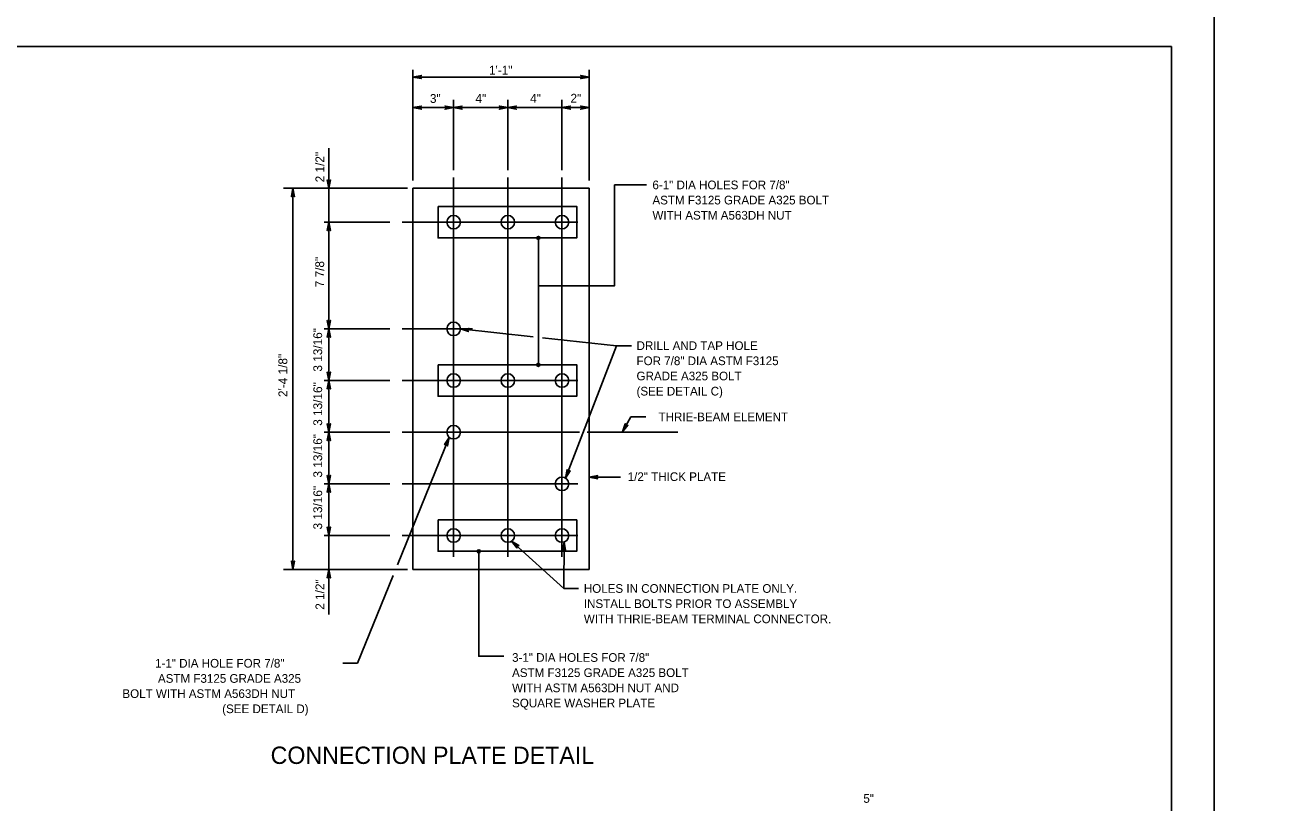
# Model space of a CAD drawing. Extents: x 632007860 to 635435983, y 295418622 to 297794622.
# Drawn here: x 634113016 to 634553598, y 296919777 to 297193122 of the extents above; entities that cross this region are included whole.
import ezdxf

# ---------------------------------------------------------------- set-up
doc = ezdxf.new("R2010")
doc.units = 0
for name, color, linetype in [('1', 7, 'Continuous'), ('8', 7, 'Continuous'), ('PLT-BNDY', 7, 'Continuous'), ('S-DETL-DIMS', 7, 'Continuous'), ('S-DETL-T120', 7, 'Continuous'), ('S-DETL-T240', 7, 'Continuous'), ('S-MISC-CNTR-WT01', 7, 'Continuous'), ('S-STEL', 7, 'Continuous')]:
    doc.layers.add(name, color=color, linetype=linetype)

msp = doc.modelspace()

# ---------------------------------------------------------------- linework, layer by layer
at = {"layer": '1'}
for p, q in [((633729860, 297185622), (634515860, 297185622)), ((634515860, 297185622), (634515860, 296621622))]:
    msp.add_line(p, q, dxfattribs=at)
at = {"layer": '8'}
for p, q in [((634263586, 297139600), (634263586, 297006215)), ((634282634, 297139600), (634282634, 297088262)), ((634301682, 297139600), (634301682, 297090518)), ((634307235, 297123867), (634245503, 297123867)), ((634301682, 297090518), (634301682, 297006215)), ((634270253, 297086359), (634245503, 297086359)), ((634282634, 297088262), (634282634, 297006215)), ((634307235, 297068203), (634245503, 297068203)), ((634307831, 297050046), (634245503, 297050046)), ((634307235, 297031889), (634245503, 297031889)), ((634307235, 297013733), (634245503, 297013733))]:
    msp.add_line(p, q, dxfattribs=at)
at = {"layer": 'PLT-BNDY'}
for points in [[(633689860, 297200622), (634530860, 297200622), (634530860, 296606622), (633689860, 296606622)], [(634530860, 297200622), (635371860, 297200622), (635371860, 296606622), (634530860, 296606622)]]:
    msp.add_lwpolyline(points, close=True, dxfattribs=at)
at = {"layer": 'S-DETL-DIMS'}
for p, q in [((634249298, 297177355), (634249298, 297138536)), ((634311207, 297177355), (634311207, 297166541)), ((634249298, 297174860), (634311207, 297174860)), ((634249298, 297164106), (634311207, 297164106)), ((634263586, 297166863), (634263586, 297142191)), ((634282634, 297166863), (634282634, 297142191)), ((634301682, 297166863), (634301682, 297142191)), ((634311207, 297166541), (634311207, 297138536)), ((634219724, 297149870), (634219724, 296985935)), ((634247344, 297135771), (634203870, 297135771)), ((634207131, 297135771), (634207131, 297001823)), ((634241169, 297123867), (634218086, 297123867)), ((634293367, 297073728), (634293367, 297118331)), ((634241169, 297086359), (634218086, 297086359)), ((634291586, 297083590), (634265967, 297086359)), ((634320837, 297080428), (634294854, 297083237)), ((634320837, 297080428), (634302891, 297033940)), ((634326048, 297080428), (634320837, 297080428)), ((634241169, 297068203), (634218086, 297068203)), ((634325883, 297055505), (634322971, 297050133)), ((634331094, 297055505), (634325883, 297055505)), ((634241169, 297050046), (634218086, 297050046)), ((634243884, 297003442), (634262071, 297048209)), ((634311207, 297014940), (634311207, 297037383)), ((634241169, 297031889), (634218086, 297031889)), ((634322182, 297034261), (634311275, 297034261)), ((634241169, 297013733), (634218086, 297013733)), ((634302322, 296995087), (634283977, 297011768)), ((634302322, 296995087), (634302411, 297011467)), ((634247344, 297001823), (634203870, 297001823)), ((634229857, 296968915), (634242354, 296999675)), ((634307532, 296995087), (634302322, 296995087)), ((634224646, 296968915), (634229857, 296968915))]:
    msp.add_line(p, q, dxfattribs=at)
for points in [[(634249298, 297174860), (634252258, 297174305), (634252144, 297174384), (634252030, 297174463), (634251971, 297174562), (634251912, 297174661), (634251895, 297174761), (634251878, 297174860), (634251895, 297174959), (634251912, 297175058), (634251971, 297175158), (634252030, 297175257), (634252144, 297175336), (634252258, 297175415), (634249298, 297174860), (634252144, 297175336), (634252030, 297175257), (634249298, 297174860), (634251971, 297175158), (634251912, 297175058), (634249298, 297174860), (634251895, 297174959), (634251878, 297174860), (634249298, 297174860), (634251895, 297174761), (634251912, 297174661), (634249298, 297174860), (634251971, 297174562), (634252030, 297174463), (634249298, 297174860), (634252144, 297174384)], [(634311207, 297174860), (634308248, 297175415), (634308362, 297175336), (634308476, 297175257), (634308535, 297175158), (634308594, 297175058), (634308611, 297174959), (634308628, 297174860), (634308611, 297174761), (634308594, 297174661), (634308535, 297174562), (634308476, 297174463), (634308362, 297174384), (634308248, 297174305), (634311207, 297174860), (634308362, 297174384), (634308476, 297174463), (634311207, 297174860), (634308535, 297174562), (634308594, 297174661), (634311207, 297174860), (634308611, 297174761), (634308628, 297174860), (634311207, 297174860), (634308611, 297174959), (634308594, 297175058), (634311207, 297174860), (634308535, 297175158), (634308476, 297175257), (634311207, 297174860), (634308362, 297175336)], [(634249298, 297164106), (634252258, 297163551), (634252144, 297163630), (634252030, 297163709), (634251971, 297163808), (634251912, 297163907), (634251895, 297164006), (634251878, 297164106), (634251895, 297164205), (634251912, 297164304), (634251971, 297164403), (634252030, 297164503), (634252144, 297164582), (634252258, 297164661), (634249298, 297164106), (634252144, 297164582), (634252030, 297164503), (634249298, 297164106), (634251971, 297164403), (634251912, 297164304), (634249298, 297164106), (634251895, 297164205), (634251878, 297164106), (634249298, 297164106), (634251895, 297164006), (634251912, 297163907), (634249298, 297164106), (634251971, 297163808), (634252030, 297163709), (634249298, 297164106), (634252144, 297163630)], [(634263586, 297164106), (634260627, 297164661), (634260741, 297164582), (634260855, 297164503), (634260913, 297164403), (634260972, 297164304), (634260989, 297164205), (634261006, 297164106), (634260989, 297164006), (634260972, 297163907), (634260913, 297163808), (634260855, 297163709), (634260741, 297163630), (634260627, 297163551), (634263586, 297164106), (634260741, 297163630), (634260855, 297163709), (634263586, 297164106), (634260913, 297163808), (634260972, 297163907), (634263586, 297164106), (634260989, 297164006), (634261006, 297164106), (634263586, 297164106), (634260989, 297164205), (634260972, 297164304), (634263586, 297164106), (634260913, 297164403), (634260855, 297164503), (634263586, 297164106), (634260741, 297164582)], [(634263586, 297164106), (634266545, 297163551), (634266431, 297163630), (634266317, 297163709), (634266258, 297163808), (634266200, 297163907), (634266183, 297164006), (634266166, 297164106), (634266183, 297164205), (634266200, 297164304), (634266258, 297164403), (634266317, 297164503), (634266431, 297164582), (634266545, 297164661), (634263586, 297164106), (634266431, 297164582), (634266317, 297164503), (634263586, 297164106), (634266258, 297164403), (634266200, 297164304), (634263586, 297164106), (634266183, 297164205), (634266166, 297164106), (634263586, 297164106), (634266183, 297164006), (634266200, 297163907), (634263586, 297164106), (634266258, 297163808), (634266317, 297163709), (634263586, 297164106), (634266431, 297163630)], [(634282634, 297164106), (634279675, 297163551), (634279789, 297163630), (634279903, 297163709), (634279962, 297163808), (634280020, 297163907), (634280037, 297164006), (634280054, 297164106), (634280037, 297164205), (634280020, 297164304), (634279962, 297164403), (634279903, 297164503), (634279789, 297164582), (634279675, 297164661), (634282634, 297164106), (634279789, 297164582), (634279903, 297164503), (634282634, 297164106), (634279962, 297164403), (634280020, 297164304), (634282634, 297164106), (634280037, 297164205), (634280054, 297164106), (634282634, 297164106), (634280037, 297164006), (634280020, 297163907), (634282634, 297164106), (634279962, 297163808), (634279903, 297163709), (634282634, 297164106), (634279789, 297163630)], [(634282634, 297164106), (634285593, 297163551), (634285479, 297163630), (634285365, 297163709), (634285307, 297163808), (634285248, 297163907), (634285231, 297164006), (634285214, 297164106), (634285231, 297164205), (634285248, 297164304), (634285307, 297164403), (634285365, 297164503), (634285479, 297164582), (634285593, 297164661), (634282634, 297164106), (634285479, 297164582), (634285365, 297164503), (634282634, 297164106), (634285307, 297164403), (634285248, 297164304), (634282634, 297164106), (634285231, 297164205), (634285214, 297164106), (634282634, 297164106), (634285231, 297164006), (634285248, 297163907), (634282634, 297164106), (634285307, 297163808), (634285365, 297163709), (634282634, 297164106), (634285479, 297163630)], [(634301682, 297164106), (634304641, 297163551), (634304527, 297163630), (634304413, 297163709), (634304355, 297163808), (634304296, 297163907), (634304279, 297164006), (634304262, 297164106), (634304279, 297164205), (634304296, 297164304), (634304355, 297164403), (634304413, 297164503), (634304527, 297164582), (634304641, 297164661), (634301682, 297164106), (634304527, 297164582), (634304413, 297164503), (634301682, 297164106), (634304355, 297164403), (634304296, 297164304), (634301682, 297164106), (634304279, 297164205), (634304262, 297164106), (634301682, 297164106), (634304279, 297164006), (634304296, 297163907), (634301682, 297164106), (634304355, 297163808), (634304413, 297163709), (634301682, 297164106), (634304527, 297163630)], [(634311207, 297164106), (634308248, 297164661), (634308362, 297164582), (634308476, 297164503), (634308535, 297164403), (634308594, 297164304), (634308611, 297164205), (634308628, 297164106), (634308611, 297164006), (634308594, 297163907), (634308535, 297163808), (634308476, 297163709), (634308362, 297163630), (634308248, 297163551), (634311207, 297164106), (634308362, 297163630), (634308476, 297163709), (634311207, 297164106), (634308535, 297163808), (634308594, 297163907), (634311207, 297164106), (634308611, 297164006), (634308628, 297164106), (634311207, 297164106), (634308611, 297164205), (634308594, 297164304), (634311207, 297164106), (634308535, 297164403), (634308476, 297164503), (634311207, 297164106), (634308362, 297164582)], [(634219724, 297135771), (634219169, 297138730), (634219248, 297138616), (634219327, 297138502), (634219426, 297138444), (634219525, 297138385), (634219625, 297138368), (634219724, 297138351), (634219823, 297138368), (634219922, 297138385), (634220021, 297138444), (634220121, 297138502), (634220200, 297138616), (634220279, 297138730), (634219724, 297135771), (634220200, 297138616), (634220121, 297138502), (634219724, 297135771), (634220021, 297138444), (634219922, 297138385), (634219724, 297135771), (634219823, 297138368), (634219724, 297138351), (634219724, 297135771), (634219625, 297138368), (634219525, 297138385), (634219724, 297135771), (634219426, 297138444), (634219327, 297138502), (634219724, 297135771), (634219248, 297138616)], [(634207131, 297135771), (634207685, 297132812), (634207606, 297132926), (634207527, 297133040), (634207428, 297133099), (634207329, 297133157), (634207230, 297133174), (634207131, 297133191), (634207031, 297133174), (634206932, 297133157), (634206833, 297133099), (634206734, 297133040), (634206655, 297132926), (634206576, 297132812), (634207131, 297135771), (634206655, 297132926), (634206734, 297133040), (634207131, 297135771), (634206833, 297133099), (634206932, 297133157), (634207131, 297135771), (634207031, 297133174), (634207131, 297133191), (634207131, 297135771), (634207230, 297133174), (634207329, 297133157), (634207131, 297135771), (634207428, 297133099), (634207527, 297133040), (634207131, 297135771), (634207606, 297132926)], [(634293367, 297101530), (634320154, 297101530), (634320154, 297136975), (634331329, 297136975)], [(634219724, 297123867), (634220279, 297120907), (634220200, 297121021), (634220121, 297121135), (634220021, 297121194), (634219922, 297121253), (634219823, 297121270), (634219724, 297121287), (634219625, 297121270), (634219525, 297121253), (634219426, 297121194), (634219327, 297121135), (634219248, 297121021), (634219169, 297120907), (634219724, 297123867), (634219248, 297121021), (634219327, 297121135), (634219724, 297123867), (634219426, 297121194), (634219525, 297121253), (634219724, 297123867), (634219625, 297121270), (634219724, 297121287), (634219724, 297123867), (634219823, 297121270), (634219922, 297121253), (634219724, 297123867), (634220021, 297121194), (634220121, 297121135), (634219724, 297123867), (634220200, 297121021)], [(634219724, 297086359), (634220279, 297089318), (634220200, 297089204), (634220121, 297089090), (634220021, 297089032), (634219922, 297088973), (634219823, 297088956), (634219724, 297088939), (634219625, 297088956), (634219525, 297088973), (634219426, 297089032), (634219327, 297089090), (634219248, 297089204), (634219169, 297089318), (634219724, 297086359), (634219248, 297089204), (634219327, 297089090), (634219724, 297086359), (634219426, 297089032), (634219525, 297088973), (634219724, 297086359), (634219625, 297088956), (634219724, 297088939), (634219724, 297086359), (634219823, 297088956), (634219922, 297088973), (634219724, 297086359), (634220021, 297089032), (634220121, 297089090), (634219724, 297086359), (634220200, 297089204)], [(634219724, 297086359), (634220279, 297083400), (634220200, 297083514), (634220121, 297083628), (634220021, 297083687), (634219922, 297083745), (634219823, 297083762), (634219724, 297083779), (634219625, 297083762), (634219525, 297083745), (634219426, 297083687), (634219327, 297083628), (634219248, 297083514), (634219169, 297083400), (634219724, 297086359), (634219248, 297083514), (634219327, 297083628), (634219724, 297086359), (634219426, 297083687), (634219525, 297083745), (634219724, 297086359), (634219625, 297083762), (634219724, 297083779), (634219724, 297086359), (634219823, 297083762), (634219922, 297083745), (634219724, 297086359), (634220021, 297083687), (634220121, 297083628), (634219724, 297086359), (634220200, 297083514)], [(634265967, 297086359), (634268974, 297086521), (634268850, 297086458), (634268727, 297086395), (634268656, 297086304), (634268584, 297086213), (634268554, 297086117), (634268524, 297086021), (634268528, 297085920), (634268532, 297085820), (634268577, 297085714), (634268623, 297085608), (634268725, 297085514), (634268828, 297085421), (634265967, 297086359), (634268725, 297085514), (634268623, 297085608), (634265967, 297086359), (634268577, 297085714), (634268532, 297085820), (634265967, 297086359), (634268528, 297085920), (634268524, 297086021), (634265967, 297086359), (634268554, 297086117), (634268584, 297086213), (634265967, 297086359), (634268656, 297086304), (634268727, 297086395), (634265967, 297086359), (634268850, 297086458)], [(634219724, 297068203), (634220279, 297071162), (634220200, 297071048), (634220121, 297070934), (634220021, 297070875), (634219922, 297070816), (634219823, 297070799), (634219724, 297070782), (634219625, 297070799), (634219525, 297070816), (634219426, 297070875), (634219327, 297070934), (634219248, 297071048), (634219169, 297071162), (634219724, 297068203), (634219248, 297071048), (634219327, 297070934), (634219724, 297068203), (634219426, 297070875), (634219525, 297070816), (634219724, 297068203), (634219625, 297070799), (634219724, 297070782), (634219724, 297068203), (634219823, 297070799), (634219922, 297070816), (634219724, 297068203), (634220021, 297070875), (634220121, 297070934), (634219724, 297068203), (634220200, 297071048)], [(634219724, 297068203), (634220279, 297065243), (634220200, 297065357), (634220121, 297065471), (634220021, 297065530), (634219922, 297065589), (634219823, 297065606), (634219724, 297065623), (634219625, 297065606), (634219525, 297065589), (634219426, 297065530), (634219327, 297065471), (634219248, 297065357), (634219169, 297065243), (634219724, 297068203), (634219248, 297065357), (634219327, 297065471), (634219724, 297068203), (634219426, 297065530), (634219525, 297065589), (634219724, 297068203), (634219625, 297065606), (634219724, 297065623), (634219724, 297068203), (634219823, 297065606), (634219922, 297065589), (634219724, 297068203), (634220021, 297065530), (634220121, 297065471), (634219724, 297068203), (634220200, 297065357)], [(634219724, 297050046), (634220279, 297053005), (634220200, 297052891), (634220121, 297052777), (634220021, 297052718), (634219922, 297052660), (634219823, 297052643), (634219724, 297052626), (634219625, 297052643), (634219525, 297052660), (634219426, 297052718), (634219327, 297052777), (634219248, 297052891), (634219169, 297053005), (634219724, 297050046), (634219248, 297052891), (634219327, 297052777), (634219724, 297050046), (634219426, 297052718), (634219525, 297052660), (634219724, 297050046), (634219625, 297052643), (634219724, 297052626), (634219724, 297050046), (634219823, 297052643), (634219922, 297052660), (634219724, 297050046), (634220021, 297052718), (634220121, 297052777), (634219724, 297050046), (634220200, 297052891)], [(634219724, 297050046), (634220279, 297047087), (634220200, 297047201), (634220121, 297047315), (634220021, 297047373), (634219922, 297047432), (634219823, 297047449), (634219724, 297047466), (634219625, 297047449), (634219525, 297047432), (634219426, 297047373), (634219327, 297047315), (634219248, 297047201), (634219169, 297047087), (634219724, 297050046), (634219248, 297047201), (634219327, 297047315), (634219724, 297050046), (634219426, 297047373), (634219525, 297047432), (634219724, 297050046), (634219625, 297047449), (634219724, 297047466), (634219724, 297050046), (634219823, 297047449), (634219922, 297047432), (634219724, 297050046), (634220021, 297047373), (634220121, 297047315), (634219724, 297050046), (634220200, 297047201)], [(634322971, 297050133), (634323894, 297052999), (634323909, 297052861), (634323924, 297052723), (634323983, 297052624), (634324042, 297052525), (634324122, 297052463), (634324201, 297052401), (634324296, 297052369), (634324391, 297052336), (634324507, 297052341), (634324622, 297052345), (634324746, 297052408), (634324869, 297052470), (634322971, 297050133), (634324746, 297052408), (634324622, 297052345), (634322971, 297050133), (634324507, 297052341), (634324391, 297052336), (634322971, 297050133), (634324296, 297052369), (634324201, 297052401), (634322971, 297050133), (634324122, 297052463), (634324042, 297052525), (634322971, 297050133), (634323983, 297052624), (634323924, 297052723), (634322971, 297050133), (634323909, 297052861)], [(634262071, 297048209), (634260437, 297045680), (634260553, 297045756), (634260669, 297045831), (634260783, 297045848), (634260898, 297045865), (634260996, 297045843), (634261094, 297045821), (634261179, 297045768), (634261265, 297045715), (634261334, 297045623), (634261404, 297045531), (634261434, 297045395), (634261464, 297045260), (634262071, 297048209), (634261434, 297045395), (634261404, 297045531), (634262071, 297048209), (634261334, 297045623), (634261265, 297045715), (634262071, 297048209), (634261179, 297045768), (634261094, 297045821), (634262071, 297048209), (634260996, 297045843), (634260898, 297045865), (634262071, 297048209), (634260783, 297045848), (634260669, 297045831), (634262071, 297048209), (634260553, 297045756)], [(634302891, 297033940), (634303479, 297036893), (634303510, 297036757), (634303541, 297036622), (634303611, 297036531), (634303681, 297036439), (634303767, 297036386), (634303852, 297036334), (634303951, 297036312), (634304049, 297036291), (634304163, 297036309), (634304277, 297036326), (634304393, 297036403), (634304509, 297036479), (634302891, 297033940), (634304393, 297036403), (634304277, 297036326), (634302891, 297033940), (634304163, 297036309), (634304049, 297036291), (634302891, 297033940), (634303951, 297036312), (634303852, 297036334), (634302891, 297033940), (634303767, 297036386), (634303681, 297036439), (634302891, 297033940), (634303611, 297036531), (634303541, 297036622), (634302891, 297033940), (634303510, 297036757)], [(634219724, 297031889), (634220279, 297034849), (634220200, 297034735), (634220121, 297034621), (634220021, 297034562), (634219922, 297034503), (634219823, 297034486), (634219724, 297034469), (634219625, 297034486), (634219525, 297034503), (634219426, 297034562), (634219327, 297034621), (634219248, 297034735), (634219169, 297034849), (634219724, 297031889), (634219248, 297034735), (634219327, 297034621), (634219724, 297031889), (634219426, 297034562), (634219525, 297034503), (634219724, 297031889), (634219625, 297034486), (634219724, 297034469), (634219724, 297031889), (634219823, 297034486), (634219922, 297034503), (634219724, 297031889), (634220021, 297034562), (634220121, 297034621), (634219724, 297031889), (634220200, 297034735)], [(634219724, 297031889), (634220279, 297028930), (634220200, 297029044), (634220121, 297029158), (634220021, 297029217), (634219922, 297029276), (634219823, 297029293), (634219724, 297029310), (634219625, 297029293), (634219525, 297029276), (634219426, 297029217), (634219327, 297029158), (634219248, 297029044), (634219169, 297028930), (634219724, 297031889), (634219248, 297029044), (634219327, 297029158), (634219724, 297031889), (634219426, 297029217), (634219525, 297029276), (634219724, 297031889), (634219625, 297029293), (634219724, 297029310), (634219724, 297031889), (634219823, 297029293), (634219922, 297029276), (634219724, 297031889), (634220021, 297029217), (634220121, 297029158), (634219724, 297031889), (634220200, 297029044)], [(634311275, 297034261), (634314235, 297034816), (634314121, 297034737), (634314007, 297034658), (634313948, 297034559), (634313889, 297034460), (634313872, 297034360), (634313855, 297034261), (634313872, 297034162), (634313889, 297034063), (634313948, 297033964), (634314007, 297033864), (634314121, 297033785), (634314235, 297033706), (634311275, 297034261), (634314121, 297033785), (634314007, 297033864), (634311275, 297034261), (634313948, 297033964), (634313889, 297034063), (634311275, 297034261), (634313872, 297034162), (634313855, 297034261), (634311275, 297034261), (634313872, 297034360), (634313889, 297034460), (634311275, 297034261), (634313948, 297034559), (634314007, 297034658), (634311275, 297034261), (634314121, 297034737)], [(634219724, 297013733), (634219169, 297016692), (634219248, 297016578), (634219327, 297016464), (634219426, 297016405), (634219525, 297016347), (634219625, 297016329), (634219724, 297016312), (634219823, 297016329), (634219922, 297016347), (634220021, 297016405), (634220121, 297016464), (634220200, 297016578), (634220279, 297016692), (634219724, 297013733), (634220200, 297016578), (634220121, 297016464), (634219724, 297013733), (634220021, 297016405), (634219922, 297016347), (634219724, 297013733), (634219823, 297016329), (634219724, 297016312), (634219724, 297013733), (634219625, 297016329), (634219525, 297016347), (634219724, 297013733), (634219426, 297016405), (634219327, 297016464), (634219724, 297013733), (634219248, 297016578)], [(634283977, 297011768), (634286568, 297010234), (634286431, 297010250), (634286293, 297010266), (634286183, 297010230), (634286074, 297010194), (634285995, 297010131), (634285917, 297010067), (634285865, 297009981), (634285812, 297009896), (634285791, 297009782), (634285770, 297009669), (634285803, 297009534), (634285837, 297009400), (634283977, 297011768), (634285803, 297009534), (634285770, 297009669), (634283977, 297011768), (634285791, 297009782), (634285812, 297009896), (634283977, 297011768), (634285865, 297009981), (634285917, 297010067), (634283977, 297011768), (634285995, 297010131), (634286074, 297010194), (634283977, 297011768), (634286183, 297010230), (634286293, 297010266), (634283977, 297011768), (634286431, 297010250)], [(634302411, 297011467), (634302966, 297008507), (634302887, 297008621), (634302808, 297008735), (634302708, 297008794), (634302609, 297008853), (634302510, 297008870), (634302411, 297008887), (634302312, 297008870), (634302212, 297008853), (634302113, 297008794), (634302014, 297008735), (634301935, 297008621), (634301856, 297008507), (634302411, 297011467), (634301935, 297008621), (634302014, 297008735), (634302411, 297011467), (634302113, 297008794), (634302212, 297008853), (634302411, 297011467), (634302312, 297008870), (634302411, 297008887), (634302411, 297011467), (634302510, 297008870), (634302609, 297008853), (634302411, 297011467), (634302708, 297008794), (634302808, 297008735), (634302411, 297011467), (634302887, 297008621)], [(634272452, 297008197), (634272452, 296971339), (634281215, 296971339)], [(634207131, 297001823), (634206576, 297004782), (634206655, 297004668), (634206734, 297004554), (634206833, 297004495), (634206932, 297004436), (634207031, 297004419), (634207131, 297004402), (634207230, 297004419), (634207329, 297004436), (634207428, 297004495), (634207527, 297004554), (634207606, 297004668), (634207685, 297004782), (634207131, 297001823), (634207606, 297004668), (634207527, 297004554), (634207131, 297001823), (634207428, 297004495), (634207329, 297004436), (634207131, 297001823), (634207230, 297004419), (634207131, 297004402), (634207131, 297001823), (634207031, 297004419), (634206932, 297004436), (634207131, 297001823), (634206833, 297004495), (634206734, 297004554), (634207131, 297001823), (634206655, 297004668)], [(634219724, 297001823), (634220279, 296998863), (634220200, 296998977), (634220121, 296999091), (634220021, 296999150), (634219922, 296999209), (634219823, 296999226), (634219724, 296999243), (634219625, 296999226), (634219525, 296999209), (634219426, 296999150), (634219327, 296999091), (634219248, 296998977), (634219169, 296998863), (634219724, 297001823), (634219248, 296998977), (634219327, 296999091), (634219724, 297001823), (634219426, 296999150), (634219525, 296999209), (634219724, 297001823), (634219625, 296999226), (634219724, 296999243), (634219724, 297001823), (634219823, 296999226), (634219922, 296999209), (634219724, 297001823), (634220021, 296999150), (634220121, 296999091), (634219724, 297001823), (634220200, 296998977)]]:
    msp.add_lwpolyline(points, dxfattribs=at)
for points in [[(634258150, 297129392), (634306891, 297129392), (634306891, 297118331), (634258150, 297118331)], [(634258150, 297073728), (634306891, 297073728), (634306891, 297062666), (634258150, 297062666)], [(634258150, 297019258), (634306891, 297019258), (634306891, 297008197), (634258150, 297008197)]]:
    msp.add_lwpolyline(points, close=True, dxfattribs=at)
for centre, radius in [((634293370, 297118327), 529), ((634293370, 297118327), 265), ((634293370, 297073729), 529), ((634293370, 297073729), 265), ((634272440, 297008193), 529), ((634272440, 297008193), 265)]:
    msp.add_circle(centre, radius, dxfattribs=at)
at = {"layer": 'S-MISC-CNTR-WT01'}
msp.add_line((634342416, 297050046), (634310469, 297050046), dxfattribs=at)
at = {"layer": 'S-STEL'}
for p, q in [((634249298, 297135771), (634249298, 297001823)), ((634311207, 297135771), (634249298, 297135771)), ((634311207, 297135771), (634311207, 297001823)), ((634311207, 297001823), (634249298, 297001823))]:
    msp.add_line(p, q, dxfattribs=at)
for centre, radius in [((634263586, 297123867), 2381), ((634282634, 297123867), 2380), ((634301682, 297123867), 2380), ((634263586, 297086359), 2381), ((634263586, 297068203), 2381), ((634282634, 297068203), 2380), ((634301682, 297068203), 2380), ((634263586, 297050046), 2381), ((634301682, 297031889), 2380), ((634263586, 297013733), 2381), ((634282634, 297013733), 2380), ((634301682, 297013733), 2380)]:
    msp.add_circle(centre, radius, dxfattribs=at)

# ---------------------------------------------------------------- texts
at = {"layer": 'S-DETL-T120'}
for s, height, p in [('1\'-1"', 3102.2, (634276014, 297175734)), ('3"', 3102.3, (634255271, 297165765)), ('4"', 3102.3, (634271269, 297165778)), ('4"', 3102.3, (634290492, 297165817)), ('2"', 3102.3, (634304655, 297165852)), ('6-1" DIA HOLES FOR 7/8" ', 3048.01, (634333458, 297135429)), ('ASTM F3125 GRADE A325 BOLT', 3048.01, (634333458, 297130095)), ('WITH ASTM A563DH NUT ', 3048.01, (634333458, 297124761)), ('DRILL AND TAP HOLE', 3048.01, (634327871, 297078949)), ('FOR 7/8" DIA ASTM F3125 ', 3048.01, (634327871, 297073615)), ('GRADE A325 BOLT', 3048.01, (634327871, 297068281)), ('(SEE DETAIL C)', 3048.01, (634327871, 297062947)), ('  THRIE-BEAM ELEMENT', 3048.01, (634333331, 297053920)), ('1/2" THICK PLATE', 3048, (634324770, 297032898)), ('HOLES IN CONNECTION PLATE ONLY.', 3048.01, (634309356, 296993608)), ('INSTALL BOLTS PRIOR TO ASSEMBLY', 3048.01, (634309356, 296988274)), ('WITH THRIE-BEAM TERMINAL CONNECTOR.', 3048.01, (634309356, 296982940)), ('1-1" DIA HOLE FOR 7/8" ', 3048.01, (634158689, 296967330)), ('3-1" DIA HOLES FOR 7/8" ', 3048.01, (634284138, 296969360)), ('ASTM F3125 GRADE A325 BOLT', 3048.01, (634284138, 296964026)), ('ASTM F3125 GRADE A325 ', 3048.01, (634159697, 296961996)), ('WITH ASTM A563DH NUT AND ', 3048.01, (634284138, 296958692)), ('BOLT WITH ASTM A563DH NUT ', 3048.01, (634147217, 296956662)), ('(SEE DETAIL D)', 3048.01, (634182282, 296951328)), ('SQUARE WASHER PLATE ', 3048.01, (634284138, 296953358)), ('5"', 3048.1, (634407569, 296919820))]:
    msp.add_text(s, height=height, dxfattribs=at).set_placement(p)
for s, p in [('2 1/2"', (634218155, 297137859)), ('7 7/8"', (634218110, 297100980)), ('3 13/16"', (634217397, 297071342)), ('2\'-4 1/8"', (634205161, 297062410)), ('3 13/16"', (634217397, 297052302)), ('3 13/16"', (634217397, 297034103)), ('3 13/16"', (634217397, 297015871)), ('2 1/2"', (634218169, 296987657))]:
    msp.add_text(s, height=3102.3, rotation=90, dxfattribs=at).set_placement(p)
at = {"layer": 'S-DETL-T240'}
msp.add_text('CONNECTION PLATE DETAIL', height=6096, dxfattribs=at).set_placement((634199297, 296933479))

doc.saveas('drawing.dxf')
